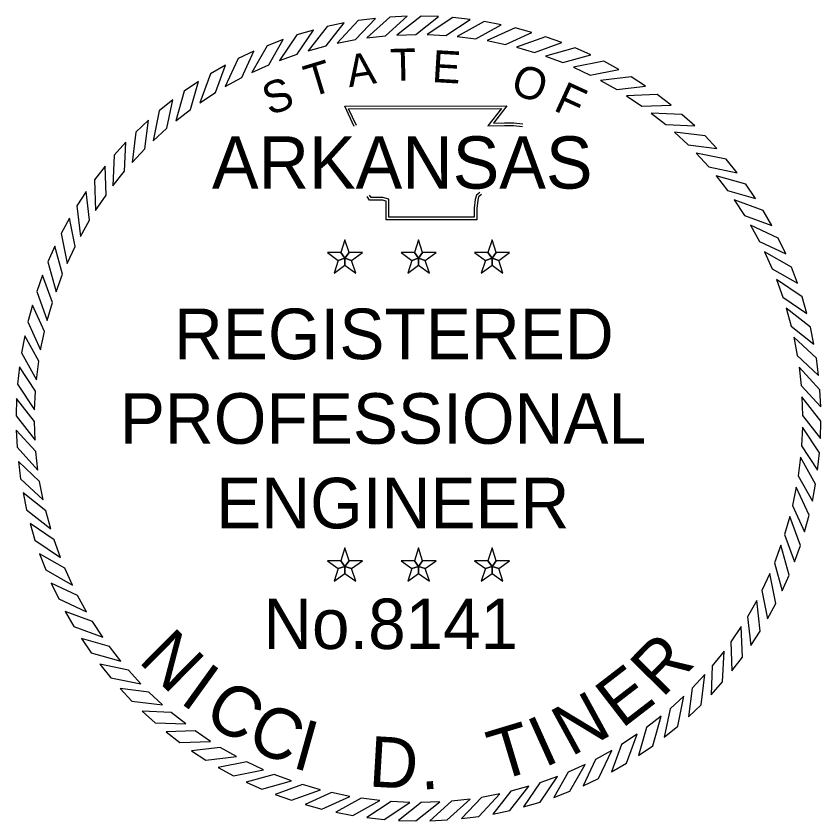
# Model space of a CAD drawing. Extents: x 759422 to 1467393, y 1662254 to 1691786.
# Drawn here: x 1467269.7 to 1467391.2, y 1691593.3 to 1691714.9 of the extents above; entities that cross this region are included whole.
import ezdxf

# ---------------------------------------------------------------- set-up
doc = ezdxf.new("R2010")
doc.units = 0
doc.layers.add('G-ANNO-SYMB', color=7, linetype='Continuous')

msp = doc.modelspace()

# ---------------------------------------------------------------- linework, layer by layer
at = {"layer": 'G-ANNO-SYMB'}
for points in [[(1467323.95, 1691714.51), (1467321.36, 1691714.18), (1467318.18, 1691710.77), (1467320.96, 1691711.3)], [(1467328.72, 1691714.84), (1467326.1, 1691714.71), (1467322.67, 1691711.56), (1467325.48, 1691711.87)], [(1467333.49, 1691714.79), (1467330.88, 1691714.86), (1467327.2, 1691711.99), (1467330.03, 1691712.08)], [(1467338.24, 1691714.36), (1467335.64, 1691714.64), (1467331.76, 1691712.07), (1467334.58, 1691711.94)], [(1467319.23, 1691713.82), (1467316.67, 1691713.28), (1467313.77, 1691709.63), (1467316.5, 1691710.38)], [(1467342.95, 1691713.56), (1467340.38, 1691714.05), (1467336.3, 1691711.79), (1467339.11, 1691711.43)], [(1467314.58, 1691712.75), (1467312.07, 1691712.02), (1467309.46, 1691708.15), (1467312.12, 1691709.11)], [(1467347.58, 1691712.4), (1467345.05, 1691713.08), (1467340.81, 1691711.15), (1467343.58, 1691710.58)], [(1467310.02, 1691711.33), (1467307.58, 1691710.39), (1467305.29, 1691706.34), (1467307.86, 1691707.5)], [(1467352.1, 1691710.88), (1467349.64, 1691711.75), (1467345.26, 1691710.16), (1467347.97, 1691709.37)], [(1467356.49, 1691709), (1467354.11, 1691710.07), (1467349.62, 1691708.83), (1467352.26, 1691707.83)], [(1467305.59, 1691709.55), (1467303.23, 1691708.43), (1467301.26, 1691704.2), (1467303.74, 1691705.57)], [(1467301.32, 1691707.43), (1467299.05, 1691706.12), (1467297.42, 1691701.76), (1467299.78, 1691703.31)], [(1467360.72, 1691706.79), (1467358.43, 1691708.04), (1467353.85, 1691707.15), (1467356.41, 1691705.95)], [(1467297.22, 1691704.97), (1467295.06, 1691703.5), (1467293.78, 1691699.02), (1467296.01, 1691700.75)], [(1467364.77, 1691704.25), (1467362.58, 1691705.68), (1467357.95, 1691705.15), (1467360.4, 1691703.76)], [(1467368.6, 1691701.41), (1467366.53, 1691703), (1467361.87, 1691702.84), (1467364.21, 1691701.25)], [(1467293.33, 1691702.21), (1467291.29, 1691700.57), (1467290.36, 1691696), (1467292.45, 1691697.91)], [(1467372.19, 1691698.27), (1467370.25, 1691700.02), (1467365.6, 1691700.22), (1467367.8, 1691698.46)], [(1467289.67, 1691699.15), (1467287.77, 1691697.35), (1467287.2, 1691692.73), (1467289.13, 1691694.79)], [(1467375.53, 1691694.86), (1467373.74, 1691696.76), (1467369.11, 1691697.32), (1467371.17, 1691695.39)], [(1467286.26, 1691695.81), (1467284.5, 1691693.87), (1467284.3, 1691689.22), (1467286.06, 1691691.42)], [(1467378.59, 1691691.19), (1467376.95, 1691693.23), (1467372.39, 1691694.16), (1467374.29, 1691692.07)], [(1467283.12, 1691692.21), (1467281.52, 1691690.14), (1467281.68, 1691685.49), (1467283.27, 1691687.82)], [(1467381.36, 1691687.3), (1467379.88, 1691689.46), (1467375.4, 1691690.74), (1467377.13, 1691688.51)], [(1467280.27, 1691688.38), (1467278.84, 1691686.19), (1467279.37, 1691681.56), (1467280.77, 1691684.02)], [(1467383.81, 1691683.21), (1467382.51, 1691685.47), (1467378.14, 1691687.1), (1467379.69, 1691684.74)], [(1467277.73, 1691684.34), (1467276.48, 1691682.04), (1467277.37, 1691677.47), (1467278.57, 1691680.03)], [(1467385.93, 1691678.93), (1467384.81, 1691681.29), (1467380.59, 1691683.26), (1467381.95, 1691680.79)], [(1467319.34, 1691678.28), (1467319.96, 1691679.14), (1467319.34, 1691681.06), (1467318.71, 1691679.14)], [(1467330.45, 1691678.28), (1467331.08, 1691679.14), (1467330.45, 1691681.06), (1467329.83, 1691679.14)], [(1467341.57, 1691678.28), (1467342.19, 1691679.14), (1467341.57, 1691681.06), (1467340.95, 1691679.14)], [(1467275.52, 1691680.11), (1467274.45, 1691677.72), (1467275.7, 1691673.23), (1467276.69, 1691675.88)], [(1467387.71, 1691674.5), (1467386.78, 1691676.94), (1467382.72, 1691679.24), (1467383.89, 1691676.66)], [(1467319.34, 1691678.28), (1467318.71, 1691679.14), (1467316.69, 1691679.14), (1467318.33, 1691677.95)], [(1467319.34, 1691678.28), (1467318.33, 1691677.95), (1467317.7, 1691676.03), (1467319.34, 1691677.22)], [(1467319.34, 1691678.28), (1467320.35, 1691677.95), (1467321.98, 1691679.14), (1467319.96, 1691679.14)], [(1467319.34, 1691678.28), (1467319.34, 1691677.22), (1467320.97, 1691676.03), (1467320.35, 1691677.95)], [(1467330.45, 1691678.28), (1467329.83, 1691679.14), (1467327.81, 1691679.14), (1467329.44, 1691677.95)], [(1467330.45, 1691678.28), (1467329.44, 1691677.95), (1467328.82, 1691676.03), (1467330.45, 1691677.22)], [(1467330.45, 1691678.28), (1467331.46, 1691677.95), (1467333.1, 1691679.14), (1467331.08, 1691679.14)], [(1467330.45, 1691678.28), (1467330.45, 1691677.22), (1467332.09, 1691676.03), (1467331.46, 1691677.95)], [(1467341.57, 1691678.28), (1467340.95, 1691679.14), (1467338.93, 1691679.14), (1467340.56, 1691677.95)], [(1467341.57, 1691678.28), (1467340.56, 1691677.95), (1467339.94, 1691676.03), (1467341.57, 1691677.22)], [(1467341.57, 1691678.28), (1467342.58, 1691677.95), (1467344.21, 1691679.14), (1467342.19, 1691679.14)], [(1467341.57, 1691678.28), (1467341.57, 1691677.22), (1467343.2, 1691676.03), (1467342.58, 1691677.95)], [(1467273.65, 1691675.72), (1467272.77, 1691673.26), (1467274.36, 1691668.88), (1467275.15, 1691671.59)], [(1467389.14, 1691669.95), (1467388.4, 1691672.45), (1467384.54, 1691675.06), (1467385.49, 1691672.4)], [(1467272.12, 1691671.2), (1467271.44, 1691668.67), (1467273.37, 1691664.43), (1467273.94, 1691667.2)], [(1467390.2, 1691665.29), (1467389.66, 1691667.85), (1467386.02, 1691670.75), (1467386.76, 1691668.03)], [(1467270.96, 1691666.57), (1467270.48, 1691664), (1467272.74, 1691659.92), (1467273.09, 1691662.72)], [(1467390.9, 1691660.57), (1467390.56, 1691663.16), (1467387.15, 1691666.34), (1467387.68, 1691663.57)], [(1467270.16, 1691661.86), (1467269.88, 1691659.26), (1467272.45, 1691655.38), (1467272.59, 1691658.2)], [(1467391.22, 1691655.81), (1467391.09, 1691658.42), (1467387.94, 1691661.85), (1467388.25, 1691659.05)], [(1467269.74, 1691657.11), (1467269.66, 1691654.49), (1467272.53, 1691650.82), (1467272.44, 1691653.64)], [(1467391.17, 1691651.03), (1467391.24, 1691653.65), (1467388.37, 1691657.32), (1467388.46, 1691654.5)], [(1467390.74, 1691646.28), (1467391.02, 1691648.88), (1467388.45, 1691652.76), (1467388.32, 1691649.94)], [(1467269.69, 1691652.33), (1467269.82, 1691649.72), (1467272.96, 1691646.29), (1467272.65, 1691649.09)], [(1467389.95, 1691641.57), (1467390.43, 1691644.14), (1467388.17, 1691648.22), (1467387.82, 1691645.42)], [(1467270.01, 1691647.57), (1467270.34, 1691644.98), (1467273.75, 1691641.8), (1467273.22, 1691644.57)], [(1467270.71, 1691642.85), (1467271.24, 1691640.29), (1467274.89, 1691637.39), (1467274.14, 1691640.11)], [(1467388.78, 1691636.94), (1467389.46, 1691639.47), (1467387.53, 1691643.71), (1467386.96, 1691640.94)], [(1467387.26, 1691632.42), (1467388.14, 1691634.88), (1467386.54, 1691639.26), (1467385.76, 1691636.55)], [(1467271.77, 1691638.19), (1467272.51, 1691635.69), (1467276.37, 1691633.08), (1467275.41, 1691635.74)], [(1467319.34, 1691631.73), (1467319.96, 1691632.59), (1467319.34, 1691634.51), (1467318.71, 1691632.59)], [(1467330.45, 1691631.73), (1467331.08, 1691632.59), (1467330.45, 1691634.51), (1467329.83, 1691632.59)], [(1467341.57, 1691631.73), (1467342.19, 1691632.59), (1467341.57, 1691634.51), (1467340.95, 1691632.59)], [(1467385.39, 1691628.03), (1467386.45, 1691630.42), (1467385.21, 1691634.91), (1467384.21, 1691632.26)], [(1467273.2, 1691633.64), (1467274.13, 1691631.2), (1467278.18, 1691628.9), (1467277.02, 1691631.48)], [(1467319.34, 1691631.73), (1467318.71, 1691632.59), (1467316.69, 1691632.59), (1467318.33, 1691631.4)], [(1467319.34, 1691631.73), (1467320.35, 1691631.4), (1467321.98, 1691632.59), (1467319.96, 1691632.59)], [(1467330.45, 1691631.73), (1467329.83, 1691632.59), (1467327.81, 1691632.59), (1467329.44, 1691631.4)], [(1467330.45, 1691631.73), (1467331.46, 1691631.4), (1467333.1, 1691632.59), (1467331.08, 1691632.59)], [(1467341.57, 1691631.73), (1467340.95, 1691632.59), (1467338.93, 1691632.59), (1467340.56, 1691631.4)], [(1467341.57, 1691631.73), (1467342.58, 1691631.4), (1467344.21, 1691632.59), (1467342.19, 1691632.59)], [(1467319.34, 1691631.73), (1467318.33, 1691631.4), (1467317.7, 1691629.48), (1467319.34, 1691630.67)], [(1467319.34, 1691631.73), (1467319.34, 1691630.67), (1467320.97, 1691629.48), (1467320.35, 1691631.4)], [(1467330.45, 1691631.73), (1467329.44, 1691631.4), (1467328.82, 1691629.48), (1467330.45, 1691630.67)], [(1467330.45, 1691631.73), (1467330.45, 1691630.67), (1467332.09, 1691629.48), (1467331.46, 1691631.4)], [(1467341.57, 1691631.73), (1467340.56, 1691631.4), (1467339.94, 1691629.48), (1467341.57, 1691630.67)], [(1467341.57, 1691631.73), (1467341.57, 1691630.67), (1467343.2, 1691629.48), (1467342.58, 1691631.4)], [(1467383.17, 1691623.8), (1467384.43, 1691626.1), (1467383.54, 1691630.67), (1467382.33, 1691628.11)], [(1467274.98, 1691629.21), (1467276.1, 1691626.85), (1467280.32, 1691624.88), (1467278.96, 1691627.35)], [(1467380.64, 1691619.76), (1467382.06, 1691621.95), (1467381.54, 1691626.58), (1467380.14, 1691624.12)], [(1467277.1, 1691624.93), (1467278.4, 1691622.67), (1467282.76, 1691621.04), (1467281.21, 1691623.4)], [(1467377.79, 1691615.93), (1467379.38, 1691618), (1467379.22, 1691622.65), (1467377.64, 1691620.32)], [(1467279.55, 1691620.84), (1467281.02, 1691618.68), (1467285.5, 1691617.4), (1467283.77, 1691619.63)], [(1467374.65, 1691612.33), (1467376.4, 1691614.27), (1467376.61, 1691618.92), (1467374.84, 1691616.72)], [(1467282.31, 1691616.95), (1467283.95, 1691614.91), (1467288.52, 1691613.98), (1467286.62, 1691616.07)], [(1467371.24, 1691608.99), (1467373.14, 1691610.79), (1467373.71, 1691615.41), (1467371.77, 1691613.35)], [(1467285.37, 1691613.28), (1467287.17, 1691611.38), (1467291.79, 1691610.82), (1467289.73, 1691612.75)], [(1467367.58, 1691605.93), (1467369.61, 1691607.57), (1467370.54, 1691612.14), (1467368.45, 1691610.23)], [(1467288.71, 1691609.87), (1467290.65, 1691608.12), (1467295.31, 1691607.92), (1467293.1, 1691609.68)], [(1467363.68, 1691603.17), (1467365.84, 1691604.64), (1467367.13, 1691609.12), (1467364.9, 1691607.39)], [(1467292.31, 1691606.73), (1467294.38, 1691605.14), (1467299.04, 1691605.3), (1467296.7, 1691606.89)], [(1467359.59, 1691600.71), (1467361.86, 1691602.02), (1467363.49, 1691606.38), (1467361.13, 1691604.83)], [(1467296.14, 1691603.89), (1467298.33, 1691602.46), (1467302.96, 1691602.99), (1467300.51, 1691604.38)], [(1467355.31, 1691598.59), (1467357.67, 1691599.71), (1467359.64, 1691603.94), (1467357.17, 1691602.58)], [(1467300.18, 1691601.35), (1467302.48, 1691600.1), (1467307.05, 1691600.99), (1467304.5, 1691602.19)], [(1467350.88, 1691596.81), (1467353.33, 1691597.75), (1467355.62, 1691601.8), (1467353.05, 1691600.64)], [(1467304.41, 1691599.14), (1467306.8, 1691598.07), (1467311.29, 1691599.31), (1467308.65, 1691600.31)], [(1467346.33, 1691595.39), (1467348.84, 1691596.12), (1467351.44, 1691599.99), (1467348.78, 1691599.03)], [(1467308.8, 1691597.26), (1467311.27, 1691596.39), (1467315.64, 1691597.98), (1467312.93, 1691598.77)], [(1467341.67, 1691594.32), (1467344.23, 1691594.86), (1467347.13, 1691598.51), (1467344.41, 1691597.76)], [(1467313.33, 1691595.74), (1467315.85, 1691595.06), (1467320.09, 1691596.99), (1467317.32, 1691597.56)], [(1467317.96, 1691594.58), (1467320.53, 1691594.09), (1467324.6, 1691596.35), (1467321.8, 1691596.71)], [(1467332.19, 1691593.3), (1467334.8, 1691593.43), (1467338.24, 1691596.58), (1467335.43, 1691596.27)], [(1467336.95, 1691593.63), (1467339.55, 1691593.96), (1467342.72, 1691597.37), (1467339.95, 1691596.84)], [(1467322.66, 1691593.78), (1467325.26, 1691593.5), (1467329.15, 1691596.07), (1467326.33, 1691596.2)], [(1467327.42, 1691593.35), (1467330.03, 1691593.28), (1467333.7, 1691596.15), (1467330.88, 1691596.06)]]:
    msp.add_lwpolyline(points, close=True, dxfattribs=at)
for points in [[(1467320.71, 1691698.19), (1467319.3, 1691701.26), (1467343.82, 1691701.28), (1467341.77, 1691698.7), (1467343.43, 1691698.72), (1467344.83, 1691698.74), (1467346.22, 1691698.59)], [(1467321.07, 1691698.35), (1467319.9, 1691700.87), (1467343.01, 1691700.89), (1467340.95, 1691698.3), (1467343.44, 1691698.33), (1467344.81, 1691698.35), (1467346.17, 1691698.2)], [(1467339.95, 1691687.92), (1467339.53, 1691687.58), (1467339.4, 1691687.07), (1467339.26, 1691685.8), (1467339.26, 1691684.1), (1467325.57, 1691684.1), (1467325.57, 1691686.39), (1467325.57, 1691686.9), (1467325.01, 1691687.07), (1467323.07, 1691687.07), (1467322.72, 1691687.6)], [(1467339.71, 1691688.22), (1467339.19, 1691687.8), (1467339.01, 1691687.14), (1467338.87, 1691685.82), (1467338.87, 1691684.49), (1467325.96, 1691684.49), (1467325.96, 1691686.39), (1467325.96, 1691687.19), (1467325.07, 1691687.46), (1467323.28, 1691687.46), (1467323.05, 1691687.81)]]:
    msp.add_lwpolyline(points, dxfattribs=at)

# ---------------------------------------------------------------- texts
for s, height, rotation, p in [('T', 4.84, 1.4789, (1467326.21, 1691705.06)), ('E', 4.84, 356.672, (1467332.4, 1691704.91)), ('A', 4.84, 8.6788, (1467319.97, 1691704.1)), ('T', 4.84, 16.9015, (1467314.09, 1691702.56)), ('O', 4.84, 341.2218, (1467344.15, 1691703.25)), ('S', 4.84, 19.7726, (1467307.94, 1691699.8)), ('F', 4.84, 335.3628, (1467350.67, 1691700.7)), ('N', 7.64, 315.2676, (1467287.98, 1691617.41)), ('R', 7.64, 45.478, (1467367.27, 1691611.73)), ('I', 7.64, 324.2141, (1467294.2, 1691611.25)), ('E', 7.64, 37.6498, (1467361.16, 1691607.11)), ('C', 7.64, 328.6873, (1467297.65, 1691608.55)), ('N', 7.64, 28.7033, (1467353.49, 1691602.91)), ('C', 7.64, 336.5155, (1467304.16, 1691604.51)), ('I', 7.64, 24.2301, (1467349.43, 1691601.27)), ('I', 7.64, 344.3437, (1467311.15, 1691601.39)), ('T', 7.64, 16.7747, (1467342.42, 1691599.25)), ('D', 7.64, 356.6451, (1467322.82, 1691598.49)), ('.', 7.64, 4.846, (1467330.83, 1691597.96))]:
    msp.add_text(s, height=height, rotation=rotation, dxfattribs=at).set_placement(p)
for s, height, p in [('ARKANSAS', 7.894, (1467299.25, 1691688.8)), ('REGISTERED', 7.642, (1467293.51, 1691663.03)), ('PROFESSIONAL', 7.6424, (1467285.33, 1691650.25)), ('ENGINEER', 7.642, (1467299.88, 1691637.47)), ('No.8141', 7.612, (1467307.01, 1691619.25))]:
    msp.add_text(s, height=height, dxfattribs=at).set_placement(p)

doc.saveas('drawing.dxf')
